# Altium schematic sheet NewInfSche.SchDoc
size A3
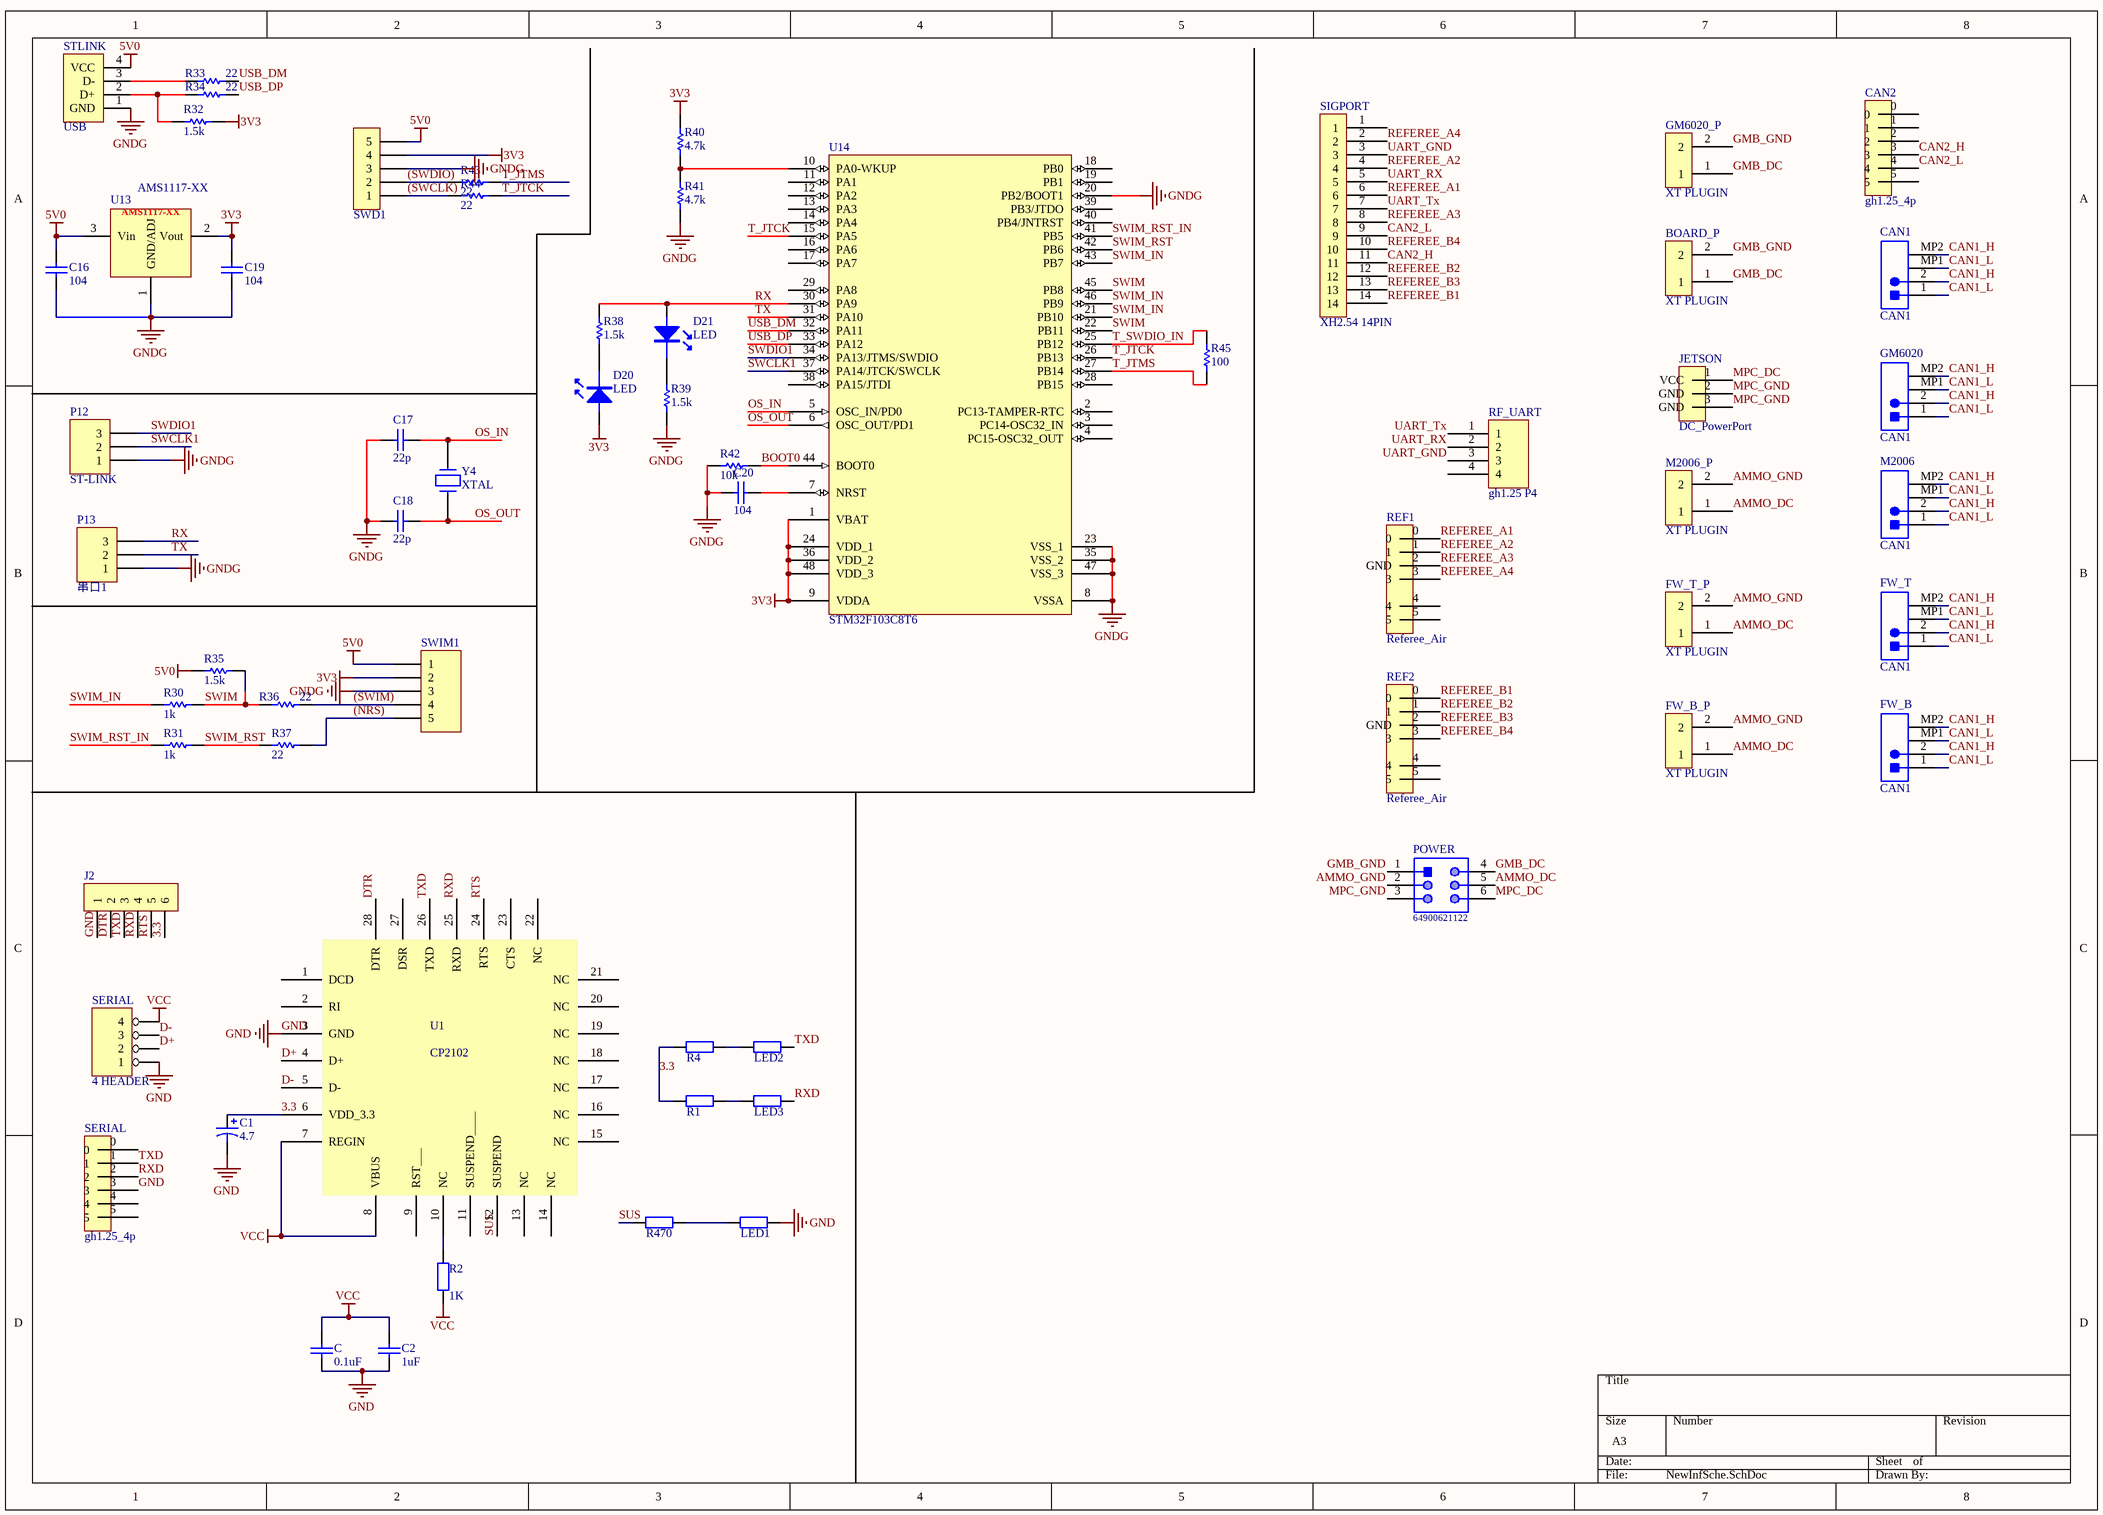
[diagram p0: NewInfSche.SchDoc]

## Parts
(Parts that share a designator on the sheet are numbered #1, #2 ... from top to bottom, then left to right.)
BOARD_P  XT PLUGIN  [XT30-M]
C  value 0.1uF  [0805]  (hidden comment: Cap)
C1  4.7  [2P-150]
C2  value 1uF  [0805]  (hidden comment: Cap)
C16  value 104  [C0805]  (hidden comment: Cap)
C17  value 22p  [C0805]  (hidden comment: Cap)
C18  value 22p  [C0805]  (hidden comment: Cap)
C19  value 104  [C0805]  (hidden comment: Cap)
C20  value 104  [C0805]  (hidden comment: Cap)
CAN1  CAN1  [JST-BM02B-GHS-TBT_V]
CAN2  gh1.25_4p  [GH1.25-LS-4P]
D20  LED  [0805_LED]
D21  LED  [0805_LED]
FW_B  CAN1  [JST-BM02B-GHS-TBT_V]
FW_B_P  XT PLUGIN  [XT30-M]
FW_T  CAN1  [JST-BM02B-GHS-TBT_V]
FW_T_P  XT PLUGIN  [XT30-M]
GM6020  CAN1  [JST-BM02B-GHS-TBT_V]
GM6020_P  XT PLUGIN  [XT30-M]
J2  (no value)  [HDR2.54-LI-6P]
JETSON  DC_PowerPort  [DC-012]
LED1  Res2  [0603]  (value not drawn)
LED2  Res2  [0603]  (value not drawn)
LED3  Res2  [0603]  (value not drawn)
M2006  CAN1  [JST-BM02B-GHS-TBT_V]
M2006_P  XT PLUGIN  [XT30-M]
P12  ST-LINK  [SIP3-1.27]
P13  串口1  [SIP3-1.27]
POWER  64900621122  [64900621122]
R1  Res2  [R]  (value not drawn)
R2  value 1K  [0805]  (hidden comment: Res2)
R4  Res2  [R]  (value not drawn)
R30  value 1k  [C0805]  (hidden comment: RES)
R31  value 1k  [C0805]  (hidden comment: RES)
R32  value 1.5k  [C0805]  (hidden comment: RES)
R33  value 22  [C0805]  (hidden comment: RES)
R34  value 22  [C0805]  (hidden comment: RES)
R35  value 1.5k  [C0805]  (hidden comment: RES)
R36  value 22  [C0805]  (hidden comment: RES)
R37  value 22  [C0805]  (hidden comment: RES)
R38  value 1.5k  [C0805]  (hidden comment: RES)
R39  value 1.5k  [C0805]  (hidden comment: RES)
R40  value 4.7k  [C0805]  (hidden comment: RES)
R41  value 4.7k  [C0805]  (hidden comment: RES)
R42  value 10k  [C0805]  (hidden comment: RES)
R43  value 22  [C0805]  (hidden comment: RES)
R44  value 22  [C0805]  (hidden comment: RES)
R45  value 100  [C0805]  (hidden comment: RES)
R470  Res2  [0805]  (value not drawn)
REF1  Referee_Air  [M8 CONNECTOR-LS]
REF2  Referee_Air  [M8 CONNECTOR-LS]
RF_UART  gh1.25 P4  [GH1.25-LS-4P]
SERIAL#1  4 HEADER  [USB-A/S_D]
SERIAL#2  gh1.25_4p  [GH1.25-LS-4P]
SIGPORT  XH2.54 14PIN  [DC-2.54-L-Z-14P]
STLINK  USB  [USB-A/S_D]
SWD1  Head5  [HDR2.54-LI-5P]  (value not drawn)
SWIM1  Header 5  [HDR2.54-LI-5P]  (value not drawn)
U1  CP2102  [CP2102]
U13  AMS1117-XX  [SOT_223]
U14  STM32F103C8T6  [LQFP48_N]
Y4  XTAL  [XTAL_2]

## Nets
3V3: C19.2 D20.1(A) R32.2 R40.2 SWD1.4 SWIM1.2 U13.2(Vout) U14.1(VBAT) U14.9(VDDA) U14.24(VDD_1) U14.36(VDD_2) U14.48(VDD_3)
5V0: C16.2 R35.1 STLINK.4(VCC) SWD1.5 SWIM1.1 U13.3(Vin)
GND: C.2 C1.2 C2.2 J2.1 LED1.1 SERIAL#1.1 SERIAL#2.3 U1.3(GND)
GNDG: C16.1 C17.1 C18.1 C19.1 C20.1 P12.1 P13.1 R39.1 R41.1 R42.1 STLINK.1(GND) SWD1.3 SWIM1.3 U13.1(GND/ADJ) U14.8(VSSA) U14.20(PB2/BOOT1) U14.23(VSS_1) U14.35(VSS_2) U14.47(VSS_3)
VCC: C.1 C2.1 R2.1 SERIAL#1.4 U1.7(REGIN) U1.8(VBUS)
3.3: C1.1 J2.6 R1.1 R4.1 U1.6(VDD_3.3)
(NRS): R37.1 SWIM1.5
(SWCLK): R44.1 SWD1.1
(SWDIO): R43.1 SWD1.2
(SWIM): R36.1 SWIM1.4
AMMO_DC: FW_B_P.1 FW_T_P.1 M2006_P.1 POWER.5
AMMO_GND: FW_B_P.2 FW_T_P.2 M2006_P.2 POWER.2
BOOT0: R42.2 U14.44(BOOT0)
CAN1_H: CAN1.2 CAN1.MP2 FW_B.2 FW_B.MP2 FW_T.2 FW_T.MP2 GM6020.2 GM6020.MP2 M2006.2 M2006.MP2
CAN1_L: CAN1.1 CAN1.MP1 FW_B.1 FW_B.MP1 FW_T.1 FW_T.MP1 GM6020.1 GM6020.MP1 M2006.1 M2006.MP1
CAN2_H: CAN2.3 SIGPORT.11
CAN2_L: CAN2.4 SIGPORT.9
D+: SERIAL#1.2 U1.4(D+)
D-: SERIAL#1.3 U1.5(D-)
DTR: J2.2 U1.28(DTR)
GMB_DC: BOARD_P.1 GM6020_P.1 POWER.4
GMB_GND: BOARD_P.2 GM6020_P.2 POWER.1
MPC_DC: JETSON.1(VCC) POWER.6
MPC_GND: JETSON.2(GND) JETSON.3(GND) POWER.3
OS_IN: C17.2 U14.5(OSC_IN/PD0) Y4.2
OS_OUT: C18.2 U14.6(OSC_OUT/PD1) Y4.1
REFEREE_A1: REF1.0 SIGPORT.6
REFEREE_A2: REF1.1 SIGPORT.4
REFEREE_A3: REF1.2(GND) SIGPORT.8
REFEREE_A4: REF1.3 SIGPORT.2
REFEREE_B1: REF2.0 SIGPORT.14
REFEREE_B2: REF2.1 SIGPORT.12
REFEREE_B3: REF2.2(GND) SIGPORT.13
REFEREE_B4: REF2.3 SIGPORT.10
RTS: J2.5 U1.24(RTS)
RX: D21.1(A) P13.3 R38.2 U14.30(PA9)
RXD: J2.4 LED3.1 SERIAL#2.2 U1.25(RXD)
SUS: R470.1 U1.12(SUSPEND)
SWCLK1: P12.2 U14.37(PA14/JTCK/SWCLK)
SWDIO1: P12.3 U14.34(PA13/JTMS/SWDIO)
SWIM: R30.2 R35.2 R36.2 U14.22(PB11) U14.45(PB8)
SWIM_IN: R30.1 U14.21(PB10) U14.43(PB7) U14.46(PB9)
SWIM_RST: R31.2 R37.2 U14.42(PB6)
SWIM_RST_IN: R31.1 U14.41(PB5)
T_JTCK: R44.2 U14.15(PA5) U14.26(PB13)
T_JTMS: R43.2 R45.1 U14.27(PB14)
T_SWDIO_IN: R45.2 U14.25(PB12)
TX: P13.2 U14.31(PA10)
TXD: J2.3 LED2.1 SERIAL#2.1 U1.26(TXD)
UART_GND: RF_UART.3 SIGPORT.3
UART_RX: RF_UART.2 SIGPORT.5
UART_Tx: RF_UART.1 SIGPORT.7
USB_DM: R33.2 U14.32(PA11)
USB_DP: R34.2 U14.33(PA12)
NetC20_2: C20.2 U14.7(NRST)
NetD20_2: D20.2(K) R38.1
NetD21_2: D21.2(K) R39.2
NetLED1_2: LED1.2 R470.2
NetLED2_2: LED2.2 R4.2
NetLED3_2: LED3.2 R1.2
NetR2_2: R2.2 U1.10(NC)
NetR32_1: R32.1 R34.1 STLINK.2(D+)
NetR33_1: R33.1 STLINK.3(D-)
NetR40_1: R40.1 R41.2 U14.10(PA0-WKUP)

Not connected (* = marked no-connect by the designer): CAN2 0 1 2 5; REF1 4 5; REF2 4 5; RF_UART 4; SERIAL#2 0 4 5; SIGPORT 1; U1 1(DCD) 2(RI) 9(RST___) 11(SUSPEND____) 13(NC) 14(NC) 15(NC) 16(NC) 17(NC) 18(NC) 19(NC) 20(NC) 21(NC) 22(NC) 23(CTS) 27(DSR); U14 2(PC13-TAMPER-RTC) 3(PC14-OSC32_IN) 4(PC15-OSC32_OUT) 11(PA1) 12(PA2) 13(PA3) 14(PA4) 16(PA6) 17(PA7) 18(PB0) 19(PB1) 28(PB15) 29(PA8) 38(PA15/JTDI) 39(PB3/JTDO) 40(PB4/JNTRST)

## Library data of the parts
C C2 = Cap: Capacitor
C1 = Cap Pol1: Polarized Capacitor (Radial); Value: 1uF
CAN1 FW_B FW_T GM6020 M2006 = CMP-2000-05957-1: Disconnectable Crimp Style Connector, Pitch 1.25 mm, 1 x 2 Position, Height 4.05 mm, -25 to 85 degC, RoHS, Tape and Reel; Manufacturer: JST-Sales-America-Inc.; Connector Type: Header,Shrouded; Number of Positions Loaded: All; Pitch: 0.049"(1.25mm); Number of Positions: 2
J2 = CON6: Connector
LED1-LED3 R1 R4 R470 = Res2: Resistor; Value: 1K
P12 P13 = Header 3: Header, 3-Pin
POWER = CMP-1502-00495-1: THT Male Header WR-MPC4, Vertical, Dual Row, pitch 4.2 mm, 6 pins; Manufacturer: Wurth Elektronik; Pin Number: 6; Pitch: 4.2mm; Working Voltage: 600VAC; Contact Resistance: 10mOhm
R2 = Res2: Resistor
SERIAL#1 = 4 HEADER: 4 Pin Header
STLINK = USB_G
SWD1 = HEAD 5
SWIM1 = Header 5: Header, 5-Pin
U1 = Component_2
U13 = AMS1117-XX: AMS   800mA LOW DROPOUT VOLTAGE REGULATOR
U14 = STM32F103C8T6: STM32 ARM-based 32-bit MCU with 64 Kbytes Flash, 48-pin LQFP, Industrial Temperature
